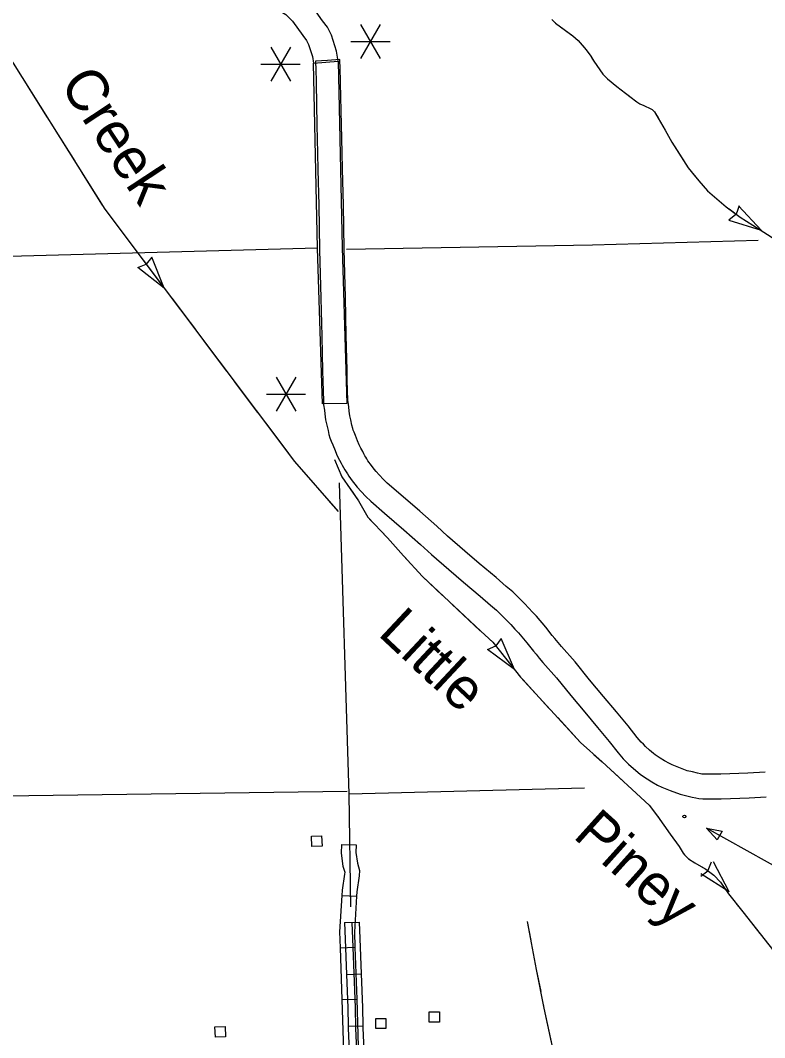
# Model space of a CAD drawing. Extents: x 1084508 to 1142749, y 1057638 to 1093403.
# Drawn here: x 1110384 to 1112766, y 1064991 to 1068244 of the extents above; entities that cross this region are included whole.
import ezdxf

# ---------------------------------------------------------------- set-up
doc = ezdxf.new("R2010")
doc.units = 0
for name, color, linetype in [('Level 10', 7, 'Continuous'), ('Level 2', 7, 'Continuous'), ('Level 32', 7, 'Continuous'), ('Level 35', 7, 'Continuous'), ('Level 4', 7, 'Continuous'), ('Level 43', 7, 'Continuous'), ('Level 48', 7, 'Continuous'), ('Level 5', 7, 'Continuous'), ('Level 56', 7, 'Continuous')]:
    doc.layers.add(name, color=color, linetype=linetype)

msp = doc.modelspace()

# ---------------------------------------------------------------- linework, layer by layer
at = {"layer": 'Level 10'}
for p, q in [((1111322.1, 1068107.1), (1111400.5, 1068113.9)), ((1111322.1, 1068107.1), (1111400.5, 1068113.9)), ((1111429.1, 1067018.8), (1111350.6, 1067017.9))]:
    msp.add_line(p, q, dxfattribs=at)
for points in [[(1111400.5, 1068113.9), (1111395.6, 1068146.1), (1111379.3, 1068196.8), (1111366.4, 1068222.7), (1111350.4, 1068242.8), (1111315.2, 1068292.5), (1111283, 1068324.8), (1111238.4, 1068352.6), (1111215.7, 1068363.3), (1111177.2, 1068375.3), (1111132.4, 1068381.1), (1111097.9, 1068383), (1110518.8, 1068377), (1110339.9, 1068371.8)], [(1110342.2, 1068293.3), (1110520.3, 1068298.5), (1111096.1, 1068304.5), (1111125.1, 1068303), (1111160.3, 1068298.4), (1111187.2, 1068289.9), (1111200.9, 1068283.6), (1111233.8, 1068263), (1111254.9, 1068241.8), (1111287.6, 1068195.7), (1111299.8, 1068180.3), (1111306.4, 1068167.1), (1111318.9, 1068128.1), (1111322.1, 1068107.1)], [(1111350.6, 1067017.9), (1111334.9, 1067515.4), (1111322.1, 1068107.1)], [(1111406.2, 1068118.6), (1111367, 1068116.1), (1111327.9, 1068113.5)], [(1111327.9, 1068113.5), (1111328.3, 1068106.7), (1111329, 1068092.4), (1111330.4, 1068043), (1111332.9, 1067908.8), (1111335.2, 1067819.4), (1111336.1, 1067766.5), (1111339.1, 1067653.1), (1111341.2, 1067510.2), (1111345.8, 1067356), (1111348.4, 1067234.8), (1111350.9, 1067123.6), (1111351.6, 1067091.7), (1111353.9, 1067026.2), (1111354.5, 1067014.4), (1111357.3, 1066998.1), (1111358.5, 1066985.8), (1111360.9, 1066966.3), (1111364.8, 1066949.5), (1111368.5, 1066932.6), (1111371.6, 1066919.4), (1111374.7, 1066909), (1111378.9, 1066898.1), (1111383.5, 1066886.9), (1111391, 1066869), (1111396.1, 1066857.2), (1111400.1, 1066847), (1111405.2, 1066838), (1111410.3, 1066828.5), (1111413.8, 1066821.8), (1111417.9, 1066814), (1111421.9, 1066807), (1111426.2, 1066800.2), (1111430.3, 1066793.6), (1111435.3, 1066786.1), (1111440.4, 1066778.8), (1111446.2, 1066771.8), (1111454.4, 1066761.3), (1111462.3, 1066750.9), (1111474.7, 1066737.4), (1111489.7, 1066721.2), (1111505.6, 1066706.1), (1111549.7, 1066667.8), (1111610.6, 1066615.2), (1111664.5, 1066567.9), (1111699.2, 1066536.4), (1111755.3, 1066487.7), (1111801.7, 1066448), (1111855.3, 1066402.7), (1111888.2, 1066373.8), (1111907.9, 1066358.2), (1111922.5, 1066343.6), (1111942.1, 1066323.5), (1111953.2, 1066312), (1111966.8, 1066297), (1111978, 1066285.8), (1112004.4, 1066254.1), (1112026.1, 1066227.3), (1112034.4, 1066217.6), (1112044.7, 1066204.8), (1112055.9, 1066191.2), (1112099.3, 1066141.7), (1112145.5, 1066085.7), (1112190.3, 1066032), (1112231.4, 1065982.8), (1112268, 1065938.6), (1112297.2, 1065901.8), (1112313.4, 1065882.5), (1112322, 1065874.1), (1112329.7, 1065866), (1112345.9, 1065851.3), (1112359.9, 1065839.5), (1112369, 1065832.2), (1112389.6, 1065818.7), (1112405.3, 1065809.2), (1112423.3, 1065798.8), (1112436.9, 1065791.7), (1112463.1, 1065781.3), (1112495.5, 1065769.5), (1112517.2, 1065764.3), (1112534.3, 1065760.3), (1112545.3, 1065758), (1112555.4, 1065756.1), (1112567.7, 1065755.2), (1112577.9, 1065754.9), (1112593.4, 1065754.7), (1112627, 1065754.7), (1112716.2, 1065758.2), (1112771.3, 1065761.4)], [(1111400.5, 1068113.9), (1111413.3, 1067517.4), (1111429.1, 1067018.8)], [(1112767.2, 1065839.8), (1112712.3, 1065836.6), (1112625.5, 1065833.2), (1112594, 1065833.2), (1112579.5, 1065833.4), (1112571.6, 1065833.6), (1112565.4, 1065834.1), (1112560.3, 1065835), (1112551.4, 1065836.9), (1112535.3, 1065840.7), (1112518.2, 1065844.7), (1112491, 1065854.6), (1112469.6, 1065863.2), (1112461, 1065867.6), (1112445.3, 1065876.7), (1112431.5, 1065885.1), (1112415.1, 1065895.7), (1112409.9, 1065900), (1112397.6, 1065910.4), (1112384.7, 1065922), (1112378, 1065929.1), (1112370.9, 1065936), (1112358, 1065951.4), (1112329, 1065988), (1112291.7, 1066033), (1112250.6, 1066082.3), (1112205.8, 1066135.8), (1112159.1, 1066192.5), (1112115.7, 1066242), (1112105.6, 1066254.3), (1112094.7, 1066267.8), (1112086.4, 1066277.5), (1112065.1, 1066303.9), (1112036.1, 1066338.7), (1112023.7, 1066351.1), (1112010.6, 1066365.6), (1111998.5, 1066378.1), (1111978.4, 1066398.7), (1111960.2, 1066416.9), (1111938.4, 1066434.1), (1111906.6, 1066462.1), (1111852.5, 1066507.8), (1111806.5, 1066547.2), (1111751.3, 1066595.1), (1111716.7, 1066626.4), (1111662.1, 1066674.4), (1111601.1, 1066727.1), (1111558.3, 1066764.2), (1111545.6, 1066776.3), (1111532.4, 1066790.6), (1111522.7, 1066801.2), (1111516.6, 1066809.2), (1111507.4, 1066820.9), (1111502.9, 1066826.3), (1111500.2, 1066830.2), (1111496.4, 1066836), (1111492.6, 1066842), (1111489.1, 1066847.7), (1111486.7, 1066851.8), (1111483.3, 1066858.3), (1111479.5, 1066865.4), (1111473.9, 1066875.8), (1111471.2, 1066880.7), (1111468.7, 1066887.1), (1111463.2, 1066899.8), (1111455.9, 1066917.1), (1111451.8, 1066927.1), (1111449, 1066934.2), (1111447.5, 1066939.5), (1111445, 1066949.9), (1111441.4, 1066966.7), (1111438.3, 1066979.9), (1111436.5, 1066994.7), (1111435, 1067008.7), (1111432.7, 1067022.9), (1111432.3, 1067029.6), (1111430.1, 1067094), (1111429.4, 1067125.4), (1111426.8, 1067236.5), (1111424.3, 1067358), (1111419.7, 1067512), (1111417.6, 1067654.7), (1111414.6, 1067768.2), (1111413.7, 1067821.1), (1111411.4, 1067910.6), (1111408.8, 1068044.9), (1111407.4, 1068095.3), (1111406.7, 1068111.1), (1111406.2, 1068118.6)]]:
    msp.add_lwpolyline(points, dxfattribs=at)
at = {"layer": 'Level 2'}
msp.add_lwpolyline([(1111441.6, 1065409.6), (1111435.8, 1065769.5), (1111405.5, 1066765)], dxfattribs=at)
at = {"layer": 'Level 32'}
for p, q in [((1111411.5, 1065609.2), (1111458.5, 1065607.7)), ((1111412.4, 1065446.1), (1111459.4, 1065443.4)), ((1111421.6, 1065359.1), (1111468.7, 1065360.5)), ((1111407.5, 1065278.4), (1111454.5, 1065280)), ((1111427.6, 1065193.2), (1111474.7, 1065195.1)), ((1111413.2, 1065112.8), (1111460.2, 1065114.4)), ((1111432.7, 1065028.2), (1111479.8, 1065028.9))]:
    msp.add_line(p, q, dxfattribs=at)
for points in [[(1111411.5, 1065609.2), (1111410.6, 1065580.8), (1111416.3, 1065539.2), (1111421.9, 1065520.1), (1111421.6, 1065513.4), (1111413.3, 1065462.2), (1111412.4, 1065446.1)], [(1111458.5, 1065607.7), (1111457.7, 1065583.3), (1111462.5, 1065549.1), (1111469.2, 1065525.9), (1111468.5, 1065508.6), (1111460.2, 1065457.1), (1111459.4, 1065443.4)], [(1111412.4, 1065446.1), (1111405.7, 1065329), (1111407.5, 1065278.4)], [(1111459.4, 1065443.4), (1111452.8, 1065328.5), (1111454.5, 1065280)], [(1111421.6, 1065359.1), (1111423.1, 1065306.4), (1111427.6, 1065193.2)], [(1111445.1, 1065359.8), (1111446.6, 1065307.2), (1111455.5, 1065087.3), (1111456.4, 1065021.6), (1111458.6, 1064973.5), (1111459.1, 1064951.9), (1111460, 1064933.9)], [(1111468.7, 1065360.5), (1111470.1, 1065308), (1111474.7, 1065195.1)], [(1111407.5, 1065278.4), (1111413.2, 1065112.8)], [(1111454.5, 1065280), (1111460.2, 1065114.4)], [(1111427.6, 1065193.2), (1111431.9, 1065086.6), (1111432.7, 1065028.2)], [(1111474.7, 1065195.1), (1111479, 1065087.9), (1111479.8, 1065028.9)], [(1111413.2, 1065112.8), (1111419.5, 1064915)], [(1111460.2, 1065114.4), (1111465.4, 1064962.9)], [(1111479.8, 1065028.9), (1111479.9, 1065022.3), (1111482.2, 1064974.2), (1111482.5, 1064957.9)], [(1111432.7, 1065028.2), (1111432.8, 1065020.9), (1111435.1, 1064972.7), (1111435.5, 1064951.1), (1111436.4, 1064933.9)]]:
    msp.add_lwpolyline(points, dxfattribs=at)
at = {"layer": 'Level 35'}
msp.add_lwpolyline([(1111401.3, 1066673.5), (1111368.8, 1066709.4)], dxfattribs=at)
at = {"layer": 'Level 4'}
for points in [[(1112744.7, 1067540), (1112215.3, 1067525), (1111427.1, 1067510.9)], [(1111334.9, 1067515.4), (1109754.8, 1067473.5)]]:
    msp.add_lwpolyline(points, dxfattribs=at)
at = {"layer": 'Level 43'}
for p, q in [((1112684.9, 1067651.4), (1112674.4, 1067624.7)), ((1112755.5, 1067572.1), (1112682.2, 1067651.1)), ((1112651.8, 1067606.5), (1112674.2, 1067624.4)), ((1112755.5, 1067572.1), (1112652.5, 1067603.9)), ((1110804.1, 1067487.4), (1110786.4, 1067464.9)), ((1110844.3, 1067387.5), (1110804.1, 1067487.4)), ((1110759.5, 1067453.9), (1110786.1, 1067464.6)), ((1110844.3, 1067387.5), (1110759.5, 1067453.9)), ((1111922.5, 1066267.3), (1111905.4, 1066244.3)), ((1111965.2, 1066168.4), (1111922.5, 1066267.3)), ((1111878.8, 1066232.6), (1111905.1, 1066244)), ((1111965.2, 1066168.4), (1111878.8, 1066232.6)), ((1112594.4, 1065552), (1112583.9, 1065525.3)), ((1112652.7, 1065457.8), (1112602, 1065552.8)), ((1112561.3, 1065507.2), (1112583.7, 1065525)), ((1112652.7, 1065457.8), (1112561.2, 1065514.8))]:
    msp.add_line(p, q, dxfattribs=at)
for points in [[(1112084.9, 1068246.6), (1112091.3, 1068240.2), (1112096.9, 1068235.3), (1112151.5, 1068194.4), (1112169.4, 1068179.6), (1112194.8, 1068149.7), (1112209.2, 1068129.6), (1112219.1, 1068113.7), (1112248, 1068071.8), (1112262.8, 1068057.4), (1112292.4, 1068033.1), (1112334.3, 1068001), (1112356.8, 1067983.7), (1112366, 1067977.4), (1112379.3, 1067971.8), (1112401.9, 1067961.5), (1112405.8, 1067958.7), (1112413.2, 1067951.7), (1112425.5, 1067931.6), (1112447.3, 1067892.8), (1112468.8, 1067854.4), (1112520.9, 1067773), (1112555.4, 1067730.7), (1112583.3, 1067698.7), (1112643.1, 1067647.6), (1112687.5, 1067614.8), (1112748.1, 1067576.8), (1112789.6, 1067549.6)], [(1112095, 1068237), (1112096.9, 1068235.3), (1112144.6, 1068199.6)], [(1110302.5, 1068198.7), (1110654.1, 1067640.4), (1111261, 1066833.4), (1111401.3, 1066673.5)], [(1112144.6, 1068199.6), (1112151.5, 1068194.4), (1112169.4, 1068179.6), (1112189, 1068156.5)], [(1112213.3, 1068123), (1112219.1, 1068113.7), (1112248, 1068071.8), (1112262.8, 1068057.4), (1112292.4, 1068033.1), (1112295.1, 1068030.9)], [(1110403.2, 1068038.8), (1110469.5, 1067933.6)], [(1112328.1, 1068005.8), (1112334.3, 1068001), (1112356.8, 1067983.7), (1112366, 1067977.4), (1112379.3, 1067971.8), (1112401.9, 1067961.5), (1112405.8, 1067958.7), (1112413.2, 1067951.7), (1112425, 1067932.3)], [(1110491.6, 1067898.5), (1110557.8, 1067793.4)], [(1112445.4, 1067896.3), (1112447.3, 1067892.8), (1112468.8, 1067854.4), (1112510, 1067790.1)], [(1110579.9, 1067758.3), (1110646.1, 1067653.1)], [(1112534.3, 1067756.7), (1112555.4, 1067730.7), (1112583.3, 1067698.7), (1112620.1, 1067667.3)], [(1112652.1, 1067641), (1112687.5, 1067614.8), (1112748.1, 1067576.8), (1112755.4, 1067572)], [(1110670, 1067619.3), (1110744.7, 1067520)], [(1110769.6, 1067486.9), (1110844.3, 1067387.5)], [(1110869.2, 1067354.4), (1110906.6, 1067304.7)], [(1110906.6, 1067304.7), (1110943.9, 1067255.1)], [(1110968.8, 1067221.9), (1111043.5, 1067122.6)], [(1111068.4, 1067089.5), (1111143.1, 1066990.1)], [(1111168, 1066957), (1111242.7, 1066857.7)], [(1111268.3, 1066825.1), (1111350.3, 1066731.7)], [(1111389.7, 1066839.5), (1111412.9, 1066784), (1111465.9, 1066708.2), (1111496.2, 1066655.2), (1111558.7, 1066588.9), (1111609.9, 1066532), (1111670.5, 1066465.7), (1111857.7, 1066290.6), (1111896.1, 1066255.7), (1111984.8, 1066143.7), (1112176.1, 1065935.3), (1112246.1, 1065872.7), (1112396.4, 1065734.6), (1112423.3, 1065699.1), (1112463.7, 1065641.8), (1112492.7, 1065602.4), (1112505.6, 1065581.4), (1112509.6, 1065575.4), (1112522.6, 1065563.4), (1112542, 1065550.5), (1112577.9, 1065529.5), (1112602.9, 1065511.1), (1112624.3, 1065488.1), (1112650.2, 1065451.2), (1112696.1, 1065393.8), (1112806.8, 1065253.2)], [(1111389.7, 1066839.5), (1111412.9, 1066784), (1111414, 1066782.4)], [(1111437.8, 1066748.5), (1111465.9, 1066708.2), (1111496.2, 1066655.2), (1111505.9, 1066644.9)], [(1111534.3, 1066614.8), (1111558.7, 1066588.9), (1111609.9, 1066532), (1111618.1, 1066523)], [(1111646.1, 1066492.4), (1111670.5, 1066465.7), (1111734.9, 1066405.5)], [(1111765.1, 1066377.2), (1111855.9, 1066292.3)], [(1111886.5, 1066264.4), (1111896.1, 1066255.7), (1111965.2, 1066168.4)], [(1111991.5, 1066136.4), (1112033.5, 1066090.6)], [(1112033.5, 1066090.6), (1112075.6, 1066044.8)], [(1112103.6, 1066014.3), (1112176.1, 1065935.3), (1112188.8, 1065923.9)], [(1112219.7, 1065896.3), (1112246.1, 1065872.7), (1112311.6, 1065812.6)], [(1112342.1, 1065784.5), (1112396.4, 1065734.6), (1112423.3, 1065699.1), (1112426.8, 1065694.3)], [(1112450.6, 1065660.4), (1112463.7, 1065641.8), (1112492.7, 1065602.4), (1112505.6, 1065581.4), (1112509.6, 1065575.4), (1112522.6, 1065563.4), (1112525.2, 1065561.7)], [(1112560.4, 1065539.8), (1112577.9, 1065529.5), (1112602.9, 1065511.1), (1112624.3, 1065488.1), (1112648.2, 1065454.1)], [(1112673.9, 1065421.6), (1112696.1, 1065393.8), (1112712.5, 1065373)], [(1112005.7, 1065362.3), (1112035.2, 1065209.5), (1112059.7, 1065085.1), (1112086.3, 1064962.3)], [(1112005.7, 1065362.3), (1112017.5, 1065301.3)], [(1112712.5, 1065373), (1112751, 1065324.1)], [(1112025.3, 1065260.6), (1112035.2, 1065209.5), (1112049.2, 1065138.6)], [(1112057.2, 1065098), (1112059.7, 1065085.1), (1112083.2, 1064976.5)]]:
    msp.add_lwpolyline(points, dxfattribs=at)
at = {"layer": 'Level 48'}
for p, q in [((1111535.5, 1068231.4), (1111472.7, 1068122.7)), ((1111472.7, 1068231.4), (1111535.5, 1068122.7)), ((1111248, 1068158.1), (1111185.2, 1068049.4)), ((1111185.2, 1068158.1), (1111248, 1068049.4)), ((1111441.3, 1068177.1), (1111566.9, 1068177.1)), ((1111153.8, 1068103.8), (1111279.4, 1068103.8)), ((1111265.4, 1067102.7), (1111202.7, 1066994)), ((1111202.7, 1067102.7), (1111265.4, 1066994)), ((1111171.3, 1067048.4), (1111296.8, 1067048.4))]:
    msp.add_line(p, q, dxfattribs=at)
at = {"layer": 'Level 5'}
for points in [[(1109782.1, 1065756.5), (1111430.2, 1065778.9)], [(1112189.7, 1065788.5), (1111435.8, 1065769.5)]]:
    msp.add_lwpolyline(points, dxfattribs=at)
at = {"layer": 'Level 56'}
for p, q in [((1112614.3, 1065623.8), (1112580.2, 1065661.2)), ((1112580.2, 1065661.2), (1112629.9, 1065651.8)), ((1112629.9, 1065651.8), (1112614.3, 1065623.8))]:
    msp.add_line(p, q, dxfattribs=at)
msp.add_lwpolyline([(1112839.8, 1065516.1), (1112580.2, 1065661.2)], dxfattribs=at)
for points in [[(1111316.6, 1065602.3), (1111315.3, 1065634.9), (1111348, 1065636.2), (1111349.3, 1065603.5)], [(1111692.5, 1065040.5), (1111692.5, 1065073.1), (1111725.2, 1065073.1), (1111725.2, 1065040.5)], [(1111521.1, 1065019.8), (1111521.1, 1065052.5), (1111553.9, 1065052.5), (1111553.9, 1065019.8)], [(1111007.9, 1064992.8), (1111006.6, 1065025.5), (1111039.3, 1065026.7), (1111040.6, 1064994.1)], [(1111007.9, 1064992.8), (1111006.6, 1065025.5), (1111039.3, 1065026.7), (1111040.6, 1064994.1)]]:
    msp.add_lwpolyline(points, close=True, dxfattribs=at)
msp.add_circle((1112509, 1065698.2), 4.71, dxfattribs=at)

# ---------------------------------------------------------------- texts
at = {"layer": 'Level 35'}
msp.add_text('Creek', height=132.58, rotation=303.3132, dxfattribs=at).set_placement((1110507.2, 1068040.4))
at = {"layer": 'Level 43'}
for s, rotation, p in [('Little', 316.8923, (1111524.8, 1066280.2)), ('Piney', 318.0412, (1112149.3, 1065633))]:
    msp.add_text(s, height=132.58, rotation=rotation, dxfattribs=at).set_placement(p)

doc.saveas('drawing.dxf')
